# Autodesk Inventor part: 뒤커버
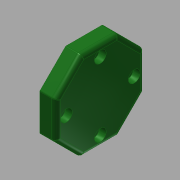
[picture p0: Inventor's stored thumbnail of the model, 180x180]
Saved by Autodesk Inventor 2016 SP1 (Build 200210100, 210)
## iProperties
Created: 2015-11
Part Number: 뒤커버
Material: 알루미늄 6061
Document SubType Name: Modeling
Designer: mduedu
Density: 1 g/cm^3
Appearance: 매끄러움 - 짙은 산림 녹색
Author: mduedu
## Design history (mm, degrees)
sketch "스케치5" dims "d66" = 60
  geometry: L1 (12.426, 30)-(30, 12.426); L2 (30, 12.426)-(30, -12.426); L3 (30, -12.426)-(12.426, -30); L4 (12.426, -30)-(-12.426, -30); L5 (-12.426, -30)-(-30, -12.426); L6 (-30, -12.426)-(-30, 12.426); L7 (-30, 12.426)-(-12.426, 30); L8 (-12.426, 30)-(12.426, 30); 4 further points
  constraints: 16 end point, 2 coincident, 2 vertical alignment, 1 midpoint, 19 other
extrude "돌출2" new body sketch "스케치5" distance "d67" = 11; taper "d68" = 0 deg
sketch "스케치6"
  geometry: C1 r 16 at (0, 0); 1 further point
  constraints: 1 centre point, 1 coincident
  dimensions: "d69" = 32 diameter of C1
extrude "돌출3" join sketch "스케치6" distance "d70" = 3; taper "d71" = 0 deg
hole "구멍5" diameter "d74" = 25; stored, may be unused: countersink angle "d78" = 90 deg, drill point angle "d80" = 0 deg; dims "d72" = 10, "d73" = 10, "d75" = 6, "d76" = 4, "d77" = 2, "d79" = 10
fillet "모깎기7" dims "d81" = 1
fillet "모깎기8" dims "d82" = 3
fillet "모깎기9" dims "d83" = 3
fillet "모깎기10" dims "d84" = 0.3
sketch "스케치7" dims "d85" = 46
  geometry: 3 further points
  constraints: 2 vertical alignment, 1 coincident, 2 other
hole "구멍6" sketch "스케치7" at (0, 23) diameter "d86" = 4.5; stored, may be unused: countersink angle "d90" = 90 deg, drill point angle "d92" = 0 deg; dims "d87" = 6, "d88" = 8, "d89" = 4.6, "d91" = 10
node "솔리드2"
pattern_circular "원형 패턴3" dims angle "d94" = 360 deg
